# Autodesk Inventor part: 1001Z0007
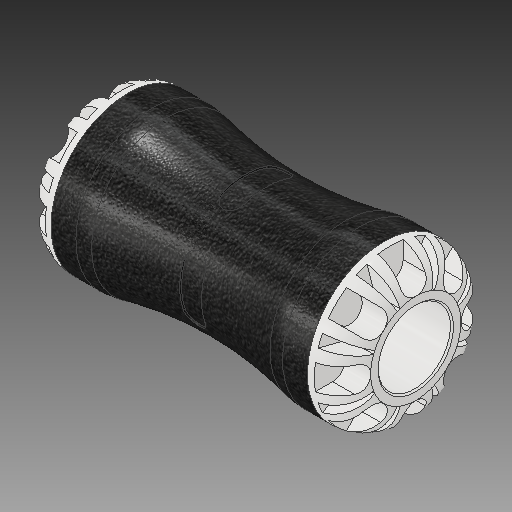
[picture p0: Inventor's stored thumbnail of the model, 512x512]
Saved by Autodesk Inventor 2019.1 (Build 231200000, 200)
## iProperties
Created: 2016-12
Part Number: 1001Z0007
Material: PVC-Piping
Description: PLASSON COUPLER 3/4''CTS x 3/4''CTS SERIES 1
Document SubType Name: Modeling
Designer: KIM
Mass: 95.2094 g
Surface Area: 200.83 cm^2
Volume: 68.0067 cm^3
Density: 1.4 g/cm^3
Appearance: White
ILogicFactory: False
Author: KIM
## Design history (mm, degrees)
derived "1001Z.ipt"
feature "Solid1::1001Z.ipt"
tag "TaggingFeature1"
body "Solid1"
other parameters: "d2" = 48.006, "d4" = 1.84167, "d11" = 7.746, "d13" = 7.746, "d14" = 0, "d16" = 360 deg, "d18" = 8 deg, "d19" = 0.442, "d20" = 8 deg, "d21" = 0.442, "d23" = 0, "d25" = 360 deg, "d27" = 18.796, "d28" = 6.63, "d29" = 6.63, "d30" = 6.63, "d31" = 0, "d33" = 0, "d37" = 19.558, "d38" = 0.4699, "d43" = 2.7625, "d44" = 22.1, "d45" = 19.558, "d46" = 39.9415, "d47" = 46.99, "d48" = 97.79, "d50" = 360 deg, "d54" = 0.513, "d_" = 22.1, "E_" = 46.99, "H_" = 97.79, "l_" = 48.006, "d12" = 27.625, "d42" = 46.99, "d52" = 9.6825
